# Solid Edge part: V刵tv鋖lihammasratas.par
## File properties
Author: Türk
Template: Iso Part.par
Last saved by: Türk
Revision: 1
Application: Solid Edge
Accuracy: 0,990
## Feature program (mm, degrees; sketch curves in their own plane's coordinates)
pattern "PatternOccurrence_1"  XOffset = 16.3636 deg
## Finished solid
Body 1: solid body, 95 faces, 270 edges, 176 vertices.
  Faces by surface: plane 48, cylinder 47
  Edges by curve: line 176, circle 94
Bounding box of the edges (mm): 50.000 x 28.000 x 50.000, from (-25, 0, -25) to (25, 28, 25).
Cylindrical faces by radius (mm): R15 x22, R17.5 x22, R20 x1, R25 x2
Planar faces by outward normal: +x 2, +y 2, -x 2, -y 2, oblique 40
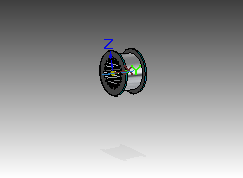
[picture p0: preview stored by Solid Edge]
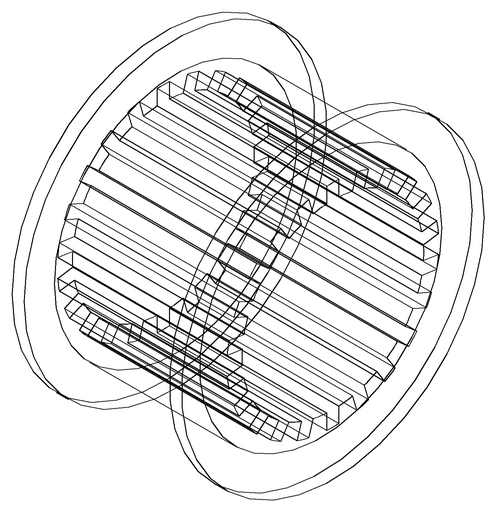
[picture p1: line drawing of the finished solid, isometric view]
